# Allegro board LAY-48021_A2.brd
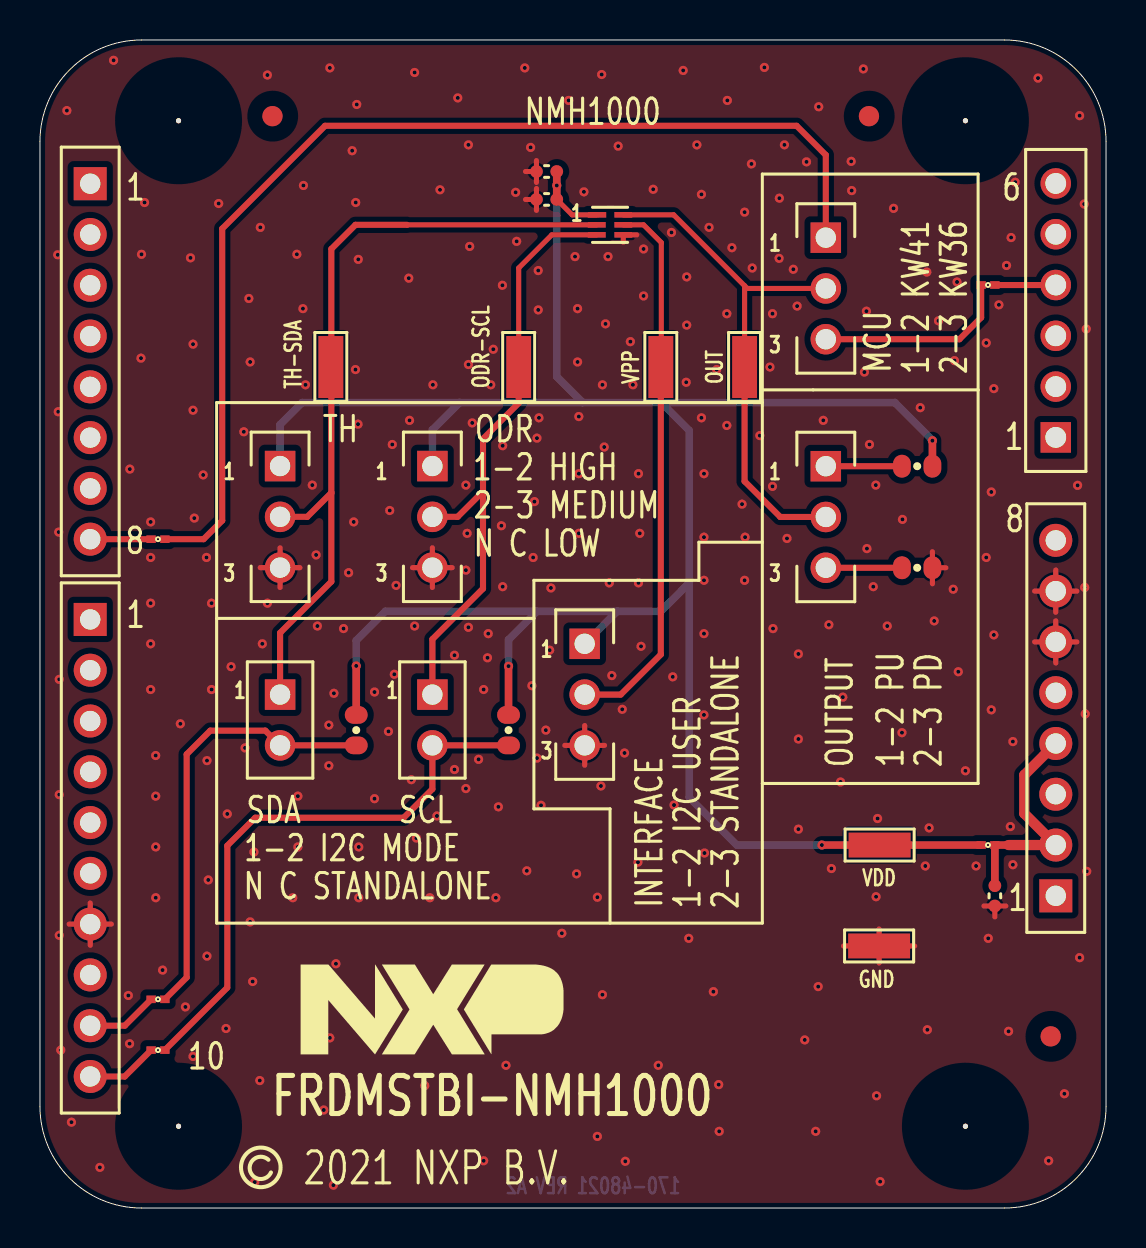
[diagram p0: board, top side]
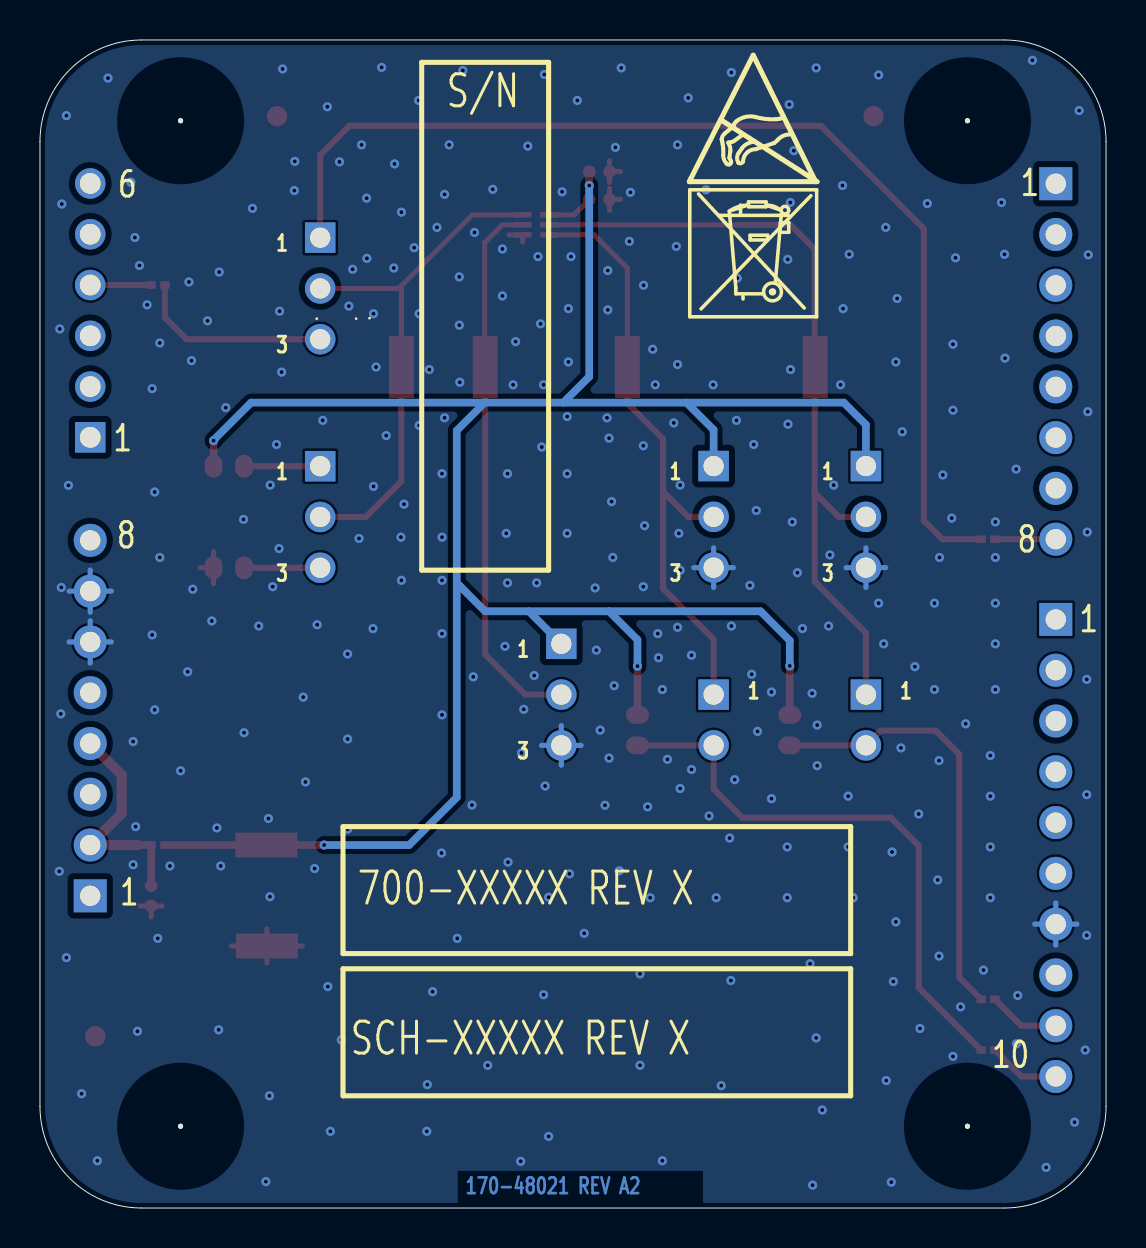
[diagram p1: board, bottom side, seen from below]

Outline 53.34 x 58.42 mm; copper layers: TOP, BOTTOM. Coordinates in mm from the lower left corner of the outline.
Outline path: 0,53.34 0,5.08 arc(1.49,1.49) 5.08,0 48.26,0 arc(51.85,1.49) 53.34,5.08 53.34,53.34 arc(51.85,56.93) 48.26,58.42 5.08,58.42 arc(1.49,56.93) 0,53.34

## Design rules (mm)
constraint set DEFAULT: min track width 0.203
nets with their own width: min track width 0.305; nets VDD

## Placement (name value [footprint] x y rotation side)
C1  0.1uF  [CC0402_25]  25.35 51.84 180 top
C2  100pF  [CC0402_25]  25.35 50.44 180 top
C3  2.2UF  [CC0402_25]  47.78 15.61 270 top
J1  HDR TH 1X3  [HDR103]  27.25 28.22 0 top
J2  HDR TH 1X3  [HDR103]  39.32 37.1 0 top
J3  SKT_1X8  [CON_SKT1X8_TH]  2.51 51.23 0 top
J4  SKT_1X6  [CON_SKT1X6_TH]  50.83 38.54 180 top
J5  SKT_1X10  [CON_SKT1X10_TH]  2.51 29.44 0 top
J6  SKT_1X8  [CON_SKT1X8_TH]  50.83 15.61 180 top
J7  HDR 1X2  [HDR102_338H]  12.01 25.68 0 top
J8  HDR 1X2  [HDR102_338H]  19.63 25.68 0 top
J9  HDR TH 1X3  [HDR103]  12.01 37.11 0 top
J10  HDR TH 1X3  [HDR103]  19.63 37.11 0 top
J11  HDR TH 1X3  [HDR103]  39.32 48.53 0 top
NOREF  -  [unnamed]  6.93 4.09 0 top
NOREF#2  -  [#2]  6.93 4.09 0 top
NOREF#3  -  [unnamed]  41.48 54.61 180 top
NOREF#4  -  [#2]  6.93 4.09 0 top
NOREF#5  -  [#2]  6.93 4.09 0 top
NOREF#6  -  [#2]  19.63 23.14 90 top
NOREF#7  -  [#2]  15.18 41.06 90 top
NOREF#8  -  [#2]  6.93 4.09 0 top
NOREF#9  -  [unnamed]  46.3 4.09 0 top
NOREF#10  -  [#2]  0 53.04 0 top
NOREF#11  -  [#2]  13.05 7.68 0 top
NOREF#12  -  [unnamed]  46.3 54.38 0 top
NOREF#13  -  [#2]  21.09 21.68 90 top
NOREF#14  -  [#2]  -140.18 -38.1 0 top
NOREF#15  -  [unnamed]  50.57 8.59 180 top
NOREF#16  -  [unnamed]  6.93 54.38 0 top
NOREF#17  -  [#2]  29.19 49.17 90 top
NOREF#18  -  [#2]  -382.6 -270.51 0 top
NOREF#19  -  [#2]  46.3 4.09 90 top
NOREF#20  -  [#2]  1.42 56.86 0 top
NOREF#21  -  [#2]  29.19 48.67 90 top
NOREF#22  -  [#2]  11.18 2.16 0 top
NOREF#23  -  [#2]  6.93 54.38 0 top
NOREF#24  -  [#2]  24.58 41.06 90 top
NOREF#25  -  [#2]  27.86 48.67 0 top
NOREF#26  -  [#2]  41.01 17.53 0 top
NOREF#27  -  [#2]  13.47 21.68 90 top
NOREF#28  -  [#2]  34.63 43.06 0 top
NOREF#29  -  [#2]  29.22 48.47 90 top
NOREF#30  -  [#2]  42.99 12.48 90 top
NOREF#31  -  [#2]  35.88 41.06 90 top
NOREF#32  -  [#2]  46.84 0 90 top
NOREF#33  -  [#2]  31.69 41.06 90 top
NOREF#34  -  [#2]  -356.12 253.79 0 top
NOREF#35  -  [#2]  13.93 43.06 0 top
NOREF#36  -  [#2]  12.01 23.14 90 top
NOREF#37  -  [#2]  43.01 17.53 90 top
NOREF#38  -  [unnamed]  11.63 54.61 180 top
NOREF#39  -  [#2]  23.33 43.06 0 top
NOREF#40  -  [#2]  10.55 21.68 0 top
NOREF#41  -  [#2]  27.82 48.47 0 top
NOREF#42  -  [#2]  18.17 21.68 0 top
NOREF#43  -  [#2]  30.44 43.06 0 top
NOREF#44  -  [#2]  229.59 -115.29 0 top
NOREF#45  -  [#2]  40.99 12.48 0 top
NOREF#46  -  [#2]  38.18 12.73 180 bottom
NOREF#47  -  [#2]  20.83 44.58 180 bottom
NOREF#48  -  [#2]  20.83 51.33 180 bottom
NOREF#49  -  [#2]  34.24 57.3 270 bottom
NOREF#50  -  [#2]  40.21 52.7 180 bottom
NOREF#51  -  [#2]  38.18 5.61 180 bottom
R1  1.0K  [RC0603_OV]  15.82 23.9 270 top
R2  1.0K  [RC0603_OV]  23.44 23.9 270 top
R3  10K  [RC0603_OV]  43.89 37.1 180 top
R4  10K  [RC0603_OV]  43.89 32.02 0 top
SH1  0  [SH0201]  5.91 33.45 180 top
SH2  0  [SH0201]  5.91 10.44 0 top
SH3  0  [SH0201]  5.91 7.9 0 top
SH4  0  [SH0201]  47.43 46.16 180 top
SH5  0  [SH0201]  47.43 18.15 0 top
TP1  0805  [TESTPOINT_122X049MIL]  42.01 18.15 0 top
TP2  0805  [TESTPOINT_122X049MIL]  41.99 13.11 0 top
TP3  0805  [TESTPOINT_122X049MIL]  31.06 42.06 90 top
TP4  0805  [TESTPOINT_122X049MIL]  14.55 42.06 90 top
TP5  0805  [TESTPOINT_122X049MIL]  23.95 42.06 90 top
TP6  0805  [TESTPOINT_122X049MIL]  35.26 42.06 90 top
U1  NMH1000  [DFN6_0P5_1P4SQ]  28.52 49.17 0 top

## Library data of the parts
C1 = CAP_NP: tolerance: 10%
C2 = CAP_NP: tolerance: 5%
C3 = CAP_NP
J1 J2 J9-J11 = CONN_HDR_3X1
J3 J6 = CONN_HDR_8X1
J4 = CONN_HDR_6X1
J5 = CONN_HDR_10X1
J7 J8 = CONN_HDR_2X1
R1-R4 = RES
SH1-SH5 = RES_SHORT-2: Tolerance: TOLERANCE; User Part Number: 470-76473
TP1-TP6 = TEST_POINT
U1 = NMH1000_6P

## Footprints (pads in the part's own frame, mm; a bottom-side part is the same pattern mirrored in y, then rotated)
CC0402_25
  round 0.635 smd: 1(-0.508,0) 2(0.508,0)
CON_SKT1X6_TH
  rect 1.524x1.524 hole 1.041: 1(0,0)
  round 1.524 hole 1.041: 2(0,-2.54) 3(0,-5.08) 4(0,-7.62) 5(0,-10.16) 6(0,-12.7)
CON_SKT1X8_TH
  rect 1.651x1.651 hole 1.016: 1(0,0)
  round 1.651 hole 1.016: 2(0,-2.54) 3(0,-5.08) 4(0,-7.62) 5(0,-10.16) 6(0,-12.7) 7(0,-15.24) 8(0,-17.78)
CON_SKT1X10_TH
  rect 1.651x1.651 hole 1.016: 1(0,0)
  round 1.651 hole 1.016: 2(0,-2.54) 3(0,-5.08) 4(0,-7.62) 5(0,-10.16) 6(0,-12.7) 7(0,-15.24) 8(0,-17.78) 9(0,-20.32) 10(0,-22.86)
DFN6_0P5_1P4SQ
  rect 0.914x0.279 smd: 1(-0.65,0.5)
  rect 0.889x0.279 smd: 2(-0.662,0) 3(-0.662,-0.5) 4(0.662,-0.5) 5(0.662,0) 6(0.662,0.5)
HDR102_338H
  rect 1.524x1.524 hole 1.016: 1(0,0)
  round 1.524 hole 1.016: 2(0,-2.54)
HDR103
  rect 1.524x1.524 hole 1.016: 1(0,0)
  round 1.524 hole 1.016: 2(0,-2.54) 3(0,-5.08)
RC0603_OV
  oval 0.889x1.143 smd: 1(-0.762,0) 2(0.762,0)
SH0201
  rect 0.47x0.381 smd: 1(-0.343,0) 2(0.343,0)
TESTPOINT_122X049MIL
  rect 3.099x1.245 smd: 1(0,0)
unnamed
  round 0.254 hole 3.175 unplated: (0,0)

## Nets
GND: C1.2 C2.2 C3.2 J1.3 J5.7 J6.6 J6.7 J9.3 J10.3 R4.2 TP2.1 U1.4(VSS)
VDD: C1.1 C2.1 J1.1 J9.1 J10.1 R1.1 R2.1 R3.1 SH5.1 TP1.1 U1.1
ODR-SCL: J8.1 J10.2 TP5.1 U1.3
OUT: J2.2 J11.2 TP6.1 U1.6
OUT_36: J11.3 SH4.2
OUT_41: J11.1 SH1.1
SCL: J8.2 R2.2 SH3.2
SDA: J7.2 R1.2 SH2.2
TH-SDA: J7.1 J9.2 TP4.1 U1.2
VPP: J1.2 TP3.1 U1.5
N16711572: J3.8 SH1.2
N16711688: J5.9 SH2.1
N16711714: J5.10 SH3.1
N16711987: J4.4 SH4.1
N16712049: C3.1 J6.2 J6.4 SH5.2
N16714153: J2.1 R3.2
N16714249: J2.3 R4.1

Pads without a net: J3 1 2 3 4 5 6 7; J4 1 2 3 5 6; J5 1 2 3 4 5 6 8; J6 1 3 5 8

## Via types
v1: diameter 0.457, hole 0.203, TOP to BOTTOM, 305 vias

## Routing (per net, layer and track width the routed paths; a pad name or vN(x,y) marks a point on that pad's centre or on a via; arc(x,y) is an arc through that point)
GND: length 62.6
  TOP w0.254: 11.02,32.03 J9.3 ; J9.3 12.01,31.04 ; J9.3 12.01,33.02 ; J9.3 13.01,32.03 ; J1.3 28.25,23.14 ; J1.3 26.26,23.14 ; J1.3 27.25,24.13 ; J1.3 27.25,22.15 ; R4.2 44.65,32.82 ; R4.2 44.65,31.22 ; R4.2 45.33,32.02 ; TP2.1 41.99,13.96 ; TP2.1 43.76,13.11 ; TP2.1 40.21,13.11 ; TP2.1 41.99,12.25 ; 47.23,15.11 C3.2 ; C3.2 48.32,15.11 ; C3.2 47.78,14.56 ; J5.7 2.51,15.25 ; J5.7 2.51,13.14 ; J5.7 3.57,14.2 ; J5.7 1.46,14.2 ; J6.7 51.88,30.85 ; J6.7 50.83,29.8 ; J6.7 49.77,30.85 ; J6.7 50.83,31.91 ; J10.3 20.63,32.03 ; J10.3 19.63,33.02 ; J10.3 19.63,31.04 ; J10.3 18.64,32.03 ; J6.6 50.83,29.37 ; J6.6 49.77,28.31 ; J6.6 51.88,28.31 ; J6.6 50.83,27.26 ; C1.2 24.84,52.39 ; C1.2 24.84,51.29 ; C1.2 24.29,51.84 ; 24.29,50.44 C2.2 ; C2.2 24.84,49.9 ; C2.2 24.84,50.99 ; 29.86,48.67 U1.4 29.19,48.31
  BOTTOM w0.254: 50.83,27.26 J6.6 ; J6.6 49.77,28.31 ; J6.6 50.83,29.37 ; J6.6 51.88,28.31 ; J1.3 27.25,24.13 ; J1.3 26.26,23.14 ; J1.3 28.25,23.14 ; J1.3 27.25,22.15 ; 19.63,31.04 J10.3 ; J10.3 20.63,32.03 ; J10.3 18.64,32.03 ; J10.3 19.63,33.02 ; 49.77,30.85 J6.7 ; J6.7 50.83,31.91 ; J6.7 51.88,30.85 ; J6.7 50.83,29.8 ; 11.02,32.03 J9.3 ; J9.3 12.01,33.02 ; J9.3 12.01,31.04 ; J9.3 13.01,32.03 ; J5.7 3.57,14.2 ; J5.7 2.51,15.25 ; J5.7 2.51,13.14 ; J5.7 1.46,14.2
  vias: v1(0.89,47.68) v1(0.91,39.83) v1(0.94,33.81) v1(0.97,26.44) v1(0.97,20.68) v1(0.97,13.64) v1(1.04,7.9) v1(1.35,54.89) v1(1.57,4.29) v1(3,2.03) v1(3.68,57.4) v1(4.42,10.63) v1(4.48,8.22) v1(4.5,36.96) v1(5.08,47.7) v1(5.05,42.51) v1(5.23,50.29) v1(5.54,34.32) v1(5.54,32.54) v1(5.54,30.25) v1(5.54,28.22) v1(5.54,25.93) v1(5.79,22.63) v1(5.79,20.6) v1(5.79,18.06) v1(5.79,15.52) v1(6.13,11.9) v1(7.02,24.22) v1(7.28,10.06) v1(7.53,47.52) v1(7.66,43.21) v1(7.66,39.9) v1(7.66,7.58) v1(7.72,34.51) v1(8.17,36.66) v1(8.33,32.54) v1(8.36,22.38) v1(8.36,12.6) v1(8.42,16.41) v1(8.59,30.25) v1(8.59,25.93) v1(8.94,50.24) v1(9.37,19.71) v1(9.31,8.98) v1(9.56,27.08) v1(10.2,38.82) v1(10.26,23.01) v1(10.45,45.49) v1(10.52,42.32) v1(10.52,14.31) v1(10.64,11.33) v1(10.71,17.81) v1(10.74,1.3) v1(11.02,49.05) v1(11,6.38) v1(11.13,28.22) v1(11.38,56.67) v1(11.38,30.25) v1(12.65,15.52) v1(12.85,47.7) v1(12.9,20.6) v1(12.9,18.06) v1(13.18,51.14) v1(13.16,44.98) v1(13.28,41.17) v1(13.63,36.16) v1(13.82,32.66) v1(13.88,29.11) v1(14.2,4.9) v1(14.45,24.16) v1(14.45,22.12) v1(14.5,57.02) v1(14.5,8.51) v1(14.68,1.14) v1(14.71,25.74) v1(14.81,12.22) v1(15.19,28.98) v1(15.44,31.78) v1(15.62,52.88) v1(15.7,34.32) v1(15.85,55.19) v1(15.8,50.29) v1(15.79,41.94) v1(15.93,47.45) v1(15.91,39.2) v1(15.95,18.06) v1(15.95,15.52) v1(16.74,25.81) v1(16.74,20.47) v1(17.44,23.84) v1(17.5,34.89) v1(17.63,38.19) v1(17.73,26.7) v1(17.82,31.14) v1(18.45,46.51) v1(18.49,39.4) v1(18.58,21.42) v1(18.75,56.79) v1(18.75,29.11) v1(18.77,11.38) v1(18.83,18.5) v1(19.25,6.12) v1(19.51,15.52) v1(19.66,41.17) v1(19.86,19.61) v1(20.02,50.93) v1(20.74,27.65) v1(20.74,21.93) v1(20.9,55.52) v1(21.31,36.16) v1(21.37,33.74) v1(21.31,31.9) v1(21.31,20.98) v1(21.44,53.17) v1(21.44,42.19) v1(21.44,29.04) v1(21.5,48.09) v1(21.63,39.27) v1(21.95,22.44) v1(22.2,25.93) v1(22.2,2.36) v1(22.43,28.73) v1(22.39,27.52) v1(22.56,41.17) v1(22.68,42.95) v1(22.81,15.52) v1(22.94,20.07) v1(23.14,46.15) v1(23.15,38.13) v1(23.09,34.12) v1(23.15,31.08) v1(23.32,11.71) v1(23.32,7.14) v1(23.8,50.8) v1(23.85,48.35) v1(24.26,57.02) v1(24.36,16.87) v1(24.55,53.05) v1(24.68,32.54) v1(24.61,26.12) v1(24.74,35.33) v1(24.87,38.51) v1(24.87,22.5) v1(24.93,46.89) v1(24.93,44.92) v1(24.97,39.52) v1(25.07,20.14) v1(25.31,23.9) v1(25.57,31.01) v1(25.5,27.9) v1(26.11,13.74) v1(26.45,55.4) v1(26.77,47.59) v1(26.85,16.71) v1(26.9,44.98) v1(26.9,42.32) v1(26.96,39.59) v1(26.96,36.73) v1(26.96,33.74) v1(27.22,50.83) v1(27.23,23.32) v1(27.89,15.54) v1(27.89,3.58) v1(28.07,21.11) v1(28.11,56.69) v1(28.14,41.17) v1(28.14,10.67) v1(28.23,38.06) v1(28.3,44.22) v1(28.42,47.59) v1(28.49,31.27) v1(28.61,26.63) v1(28.93,53.11) v1(29.13,24.94) v1(29.25,22.76) v1(29.29,2.34) v1(29.54,43.33) v1(29.67,41.17) v1(29.95,36.73) v1(29.95,31.27) v1(29.92,17.3) v1(30.01,33.74) v1(30.07,28.09) v1(30.2,47.97) v1(30.2,45.62) v1(30.68,50.95) v1(30.94,7.14) v1(31.6,48.79) v1(31.66,26.57) v1(31.72,20.15) v1(32.18,56.9) v1(32.36,46.57) v1(32.36,44.16) v1(32.33,41.3) v1(32.46,13.49) v1(32.87,53.17) v1(33.1,50.7) v1(33.1,39.52) v1(33.22,36.73) v1(33.22,33.55) v1(33.22,31.39) v1(33.22,28.73) v1(33.22,24.66) v1(33.25,17.75) v1(33.48,49.05) v1(33.69,10.82) v1(33.86,41.94) v1(33.96,6.17) v1(33.99,3.84) v1(34.37,44.73) v1(34.37,39.14) v1(34.39,55.4) v1(34.62,48.03) v1(35.13,35.2) v1(35.26,49.81) v1(35.28,33.55) v1(35.26,31.39) v1(35.6,52.22) v1(35.64,47.02) v1(36.02,38.63) v1(36.25,57.05) v1(36.53,42.06) v1(36.65,44.73) v1(36.65,36.09) v1(36.68,28.98) v1(36.98,47.5) v1(37,50.51) v1(37.25,53.17) v1(37.38,33.49) v1(37.69,46.95) v1(37.88,45.11) v1(37.95,27.71) v1(37.95,23.46) v1(37.95,18.95) v1(38.27,8.41) v1(38.35,52.32) v1(38.81,3.84) v1(38.96,55.08) v1(38.94,11.07) v1(39.19,39.4) v1(39.47,29.17) v1(39.6,16.98) v1(40.06,21.31) v1(40.17,25.55) v1(40.59,52.35) v1(40.61,50.89) v1(41.2,56.97) v1(41.25,41.81) v1(41.35,44.86) v1(41.38,32.98) v1(41.5,38.19) v1(41.69,31.08) v1(41.82,36.16) v1(41.83,15.57) v1(41.86,5.61) v1(41.91,19.48) v1(42.04,1.32) v1(42.39,29.11) v1(42.71,50) v1(43.15,34.44) v1(43.13,23.77) v1(44.04,40.03) v1(44.37,46.81) v1(44.3,17.11) v1(44.4,8.92) v1(44.49,19.01) v1(44.74,29.36) v1(44.96,44.37) v1(45.76,42.38) v1(45.69,30.95) v1(45.89,46.32) v1(45.95,26.82) v1(46.3,21.87) v1(46.84,17.11) v1(47.35,43.27) v1(47.35,32.54) v1(47.45,13.49) v1(47.6,35.81) v1(47.6,24.92) v1(47.73,40.98) v1(47.73,28.66) v1(47.98,45.17) v1(48.36,47.14) v1(48.46,8.84) v1(48.55,19.08) v1(48.59,48.54) v1(48.68,23.33) v1(48.68,17.17) v1(48.79,51.31) v1(49.94,56.52) v1(50.47,2.36) v1(51.26,5.71) v1(51.92,36.14) v1(52.02,54.64) v1(52.02,12.52) v1(52.25,50.22) v1(52.27,31.04) v1(52.35,43.97) v1(52.3,24.71) v1(52.37,16.84)
VDD: length 121.7
  TOP w0.254: C2.1 26.63,49.67 U1.1
  TOP w0.381: C2.1 v1(25.86,51.14) C1.1 ; v1(39.12,18.15) TP1.1 SH5.1 ; v1(15.82,27.11) R1.1 ; R3.1 v1(44.65,38.38) ; v1(23.44,27.1) R2.1
  BOTTOM w0.381: 20.99,40.28 19.63,38.93 J10.1 ; 20.99,40.28 13.12,40.28 12.01,39.18 J9.1 ; 20.99,40.28 27.15,40.28 ; 28.88,29.85 J1.1 ; 28.88,29.85 31.06,29.85 32.49,31.27 ; 28.88,29.85 24.87,29.85 ; 31.09,40.28 42.77,40.28 44.65,38.4 v1(44.65,38.38) ; 31.09,40.28 27.15,40.28 ; 31.09,40.28 32.49,38.89 32.49,31.27 ; 24.87,29.85 17.28,29.85 15.82,28.38 v1(15.82,27.11) ; 24.87,29.85 23.44,28.42 v1(23.44,27.1) ; 27.15,40.28 25.86,41.58 v1(25.86,51.14) ; 32.49,31.27 32.49,20.54 34.87,18.15 v1(39.12,18.15)
ODR-SCL: length 30.8
  TOP w0.254: U1.3 25.61,48.67 23.95,47.02 TP5.1
  TOP w0.305: 22.17,35.84 22.17,30.98 19.63,28.45 J8.1 ; 22.17,35.84 20.9,34.57 J10.2 ; 22.17,35.84 22.17,38.47 23.95,40.26 TP5.1
OUT: length 26.2
  TOP w0.254: 35.26,46.13 31.71,49.67 U1.6 ; 35.26,46.13 TP6.1 ; 35.26,46.13 35.39,45.99 J11.2
  TOP w0.305: J2.2 37.04,34.56 35.26,36.35 TP6.1
OUT_36: length 9.8
  TOP w0.305: J11.3 46.01,43.45 47.09,44.54 SH4.2
OUT_41: length 54.9
  TOP w0.305: SH1.1 8.19,33.45 9.12,34.38 9.12,48.98 14.26,54.13 37.86,54.13 39.32,52.67 J11.1
SCL: length 28.9
  TOP w0.305: SH3.2 9.37,11.02 9.37,18.12 10.77,19.52 18.2,19.52 19.63,20.96 J8.2 R2.2
SDA: length 22
  TOP w0.305: R1.2 J7.2 11.28,23.88 8.52,23.88 7.34,22.69 7.34,11.53 SH2.2
TH-SDA: length 40.2
  TOP w0.254: 18.36,49.17 U1.2
  TOP w0.305: 14.58,35.78 14.58,31.33 12.01,28.77 J7.1 ; 14.58,35.78 14.58,42.04 TP4.1 14.58,42.09 14.58,47.97 15.79,49.17 18.36,49.17 ; 14.58,35.78 13.37,34.57 J9.2
VPP: length 27.5
  TOP w0.254: 31.06,42.19 31.09,42.21 31.09,48.29 30.2,49.17 U1.5
  TOP w0.305: 31.06,42.19 TP3.1 31.06,27.69 29.06,25.68 J1.2
N16711572: length 3
  TOP w0.305: J3.8 SH1.2
N16711688: length 3.6
  TOP w0.305: SH2.1 4.24,9.12 J5.9
N16711714: length 3.6
  TOP w0.305: J5.10 4.24,6.58 SH3.1
N16711987: length 3
  TOP w0.305: J4.4 SH4.1
N16712049: length 11.5
  TOP w0.381: 48.46,18.15 SH5.2 C3.1
  TOP w0.508: 48.46,18.15 J6.2 49.25,19.73 49.25,21.66 J6.4
N16714153: length 3.8
  TOP w0.305: J2.1 R3.2
N16714249: length 3.8
  TOP w0.305: J2.3 R4.1

Small or netless copper shapes (teardrops, artwork), in the pictures only: 1 on TOP, 1 on BOTTOM

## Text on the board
BOTTOM: 170-48021 REV A2 | 5 OF 8 | L2 SS
Board Geometry/Soldermask Bottom: 6 OF 8 | SECONDARY SOLDERMASK
Ref Des/Silkscreen Bottom: 7 OF 8 | SECONDARY SILKSCREEN
User.Comments: 1 OF 1 | TEST PROBE | 1/1 | 1
TOP: 4 OF 8 | L1 PS
Board Geometry/Soldermask Top: 3 OF 8 | PRIMARY SOLDERMASK
Ref Des/Silkscreen Top: N C STANDALONE | 1-2 I2C MODE | SDA | TH | SCL | 1-2 HIGH | 2-3 MEDIUM | N C LOW | ODR | NMH1000 | INTERFACE | 1-2 I2C USER | 2-3 STANDALONE | OUTPUT | MCU | 1-2 PU | 1-2 KW41 | 2-3 PD | 2-3 KW36 | 2 OF 8 | PRIMARY SILKSCREEN | FRDMSTBI-NMH1000
XSECTION_CHART: INTENTIONAL 5 SHORTS AT: | Location           RefDes      Net 1            Net 2 | (-40.50 1156.01)    SH1       N16711572     &  OUT_41 | (-40.50 250.00)     SH2       N16711688     &  SDA | (-40.50 150.00)     SH3       N16711714     &  SCL | (1594.50 1656.50)   SH4       N16711987     &  OUT_36 | (1594.50 553.74)    SH5       N16712049     &  VDD | 16 | 17 | 8 | 22. | *  SURFACE - AIR 0 MIL | *  DIELECTRIC - DRY_FILM_MASK 3 MIL | L1 TOP CONDUCTOR - 1OZ_COPPER 1.2 MIL | *  DIELECTRIC - FR-4 54 MIL | L2 BOTTOM CONDUCTOR - 1OZ_COPPER 1.2 MIL | DESIGN CROSS SECTION CHART | ___________________________ | TOTAL THICKNESS 62.4 MIL | 1-2
DIMENSION: PRIMARY DATUM | GRID ORIGIN
BODY_CENTER: 1 OF 8 | PRIMARY PASTEMASK
PASTEMASK_BOTTOM: 8 OF 8 | SECONDARY PASTEMASK
User.9: 2 OF 8 | 7 OF 8 | SECONDARY SILKSCREEN | PRIMARY SILKSCREEN
User.10: 1 | 8
User.20: 07-21-21 | 02-07-21 | R.Y. | A1 | A2 | SILKSCREEN & MINOR CHANGE | SILKSCREEN CHANGE
User.24: FIGURE | FINISHED_SIZE | 8.0 | 40.0 | 41.0 | 125.0 | DRILL CHART: TOP to BOTTOM | ALL UNITS ARE IN MILS | TOLERANCE_DRILL | +0.0/-8.0 | +3.0/-3.0 | +2.0/-2.0 | PLATED | NON-PLATED | QTY | 305 | 45 | 6 | 4
